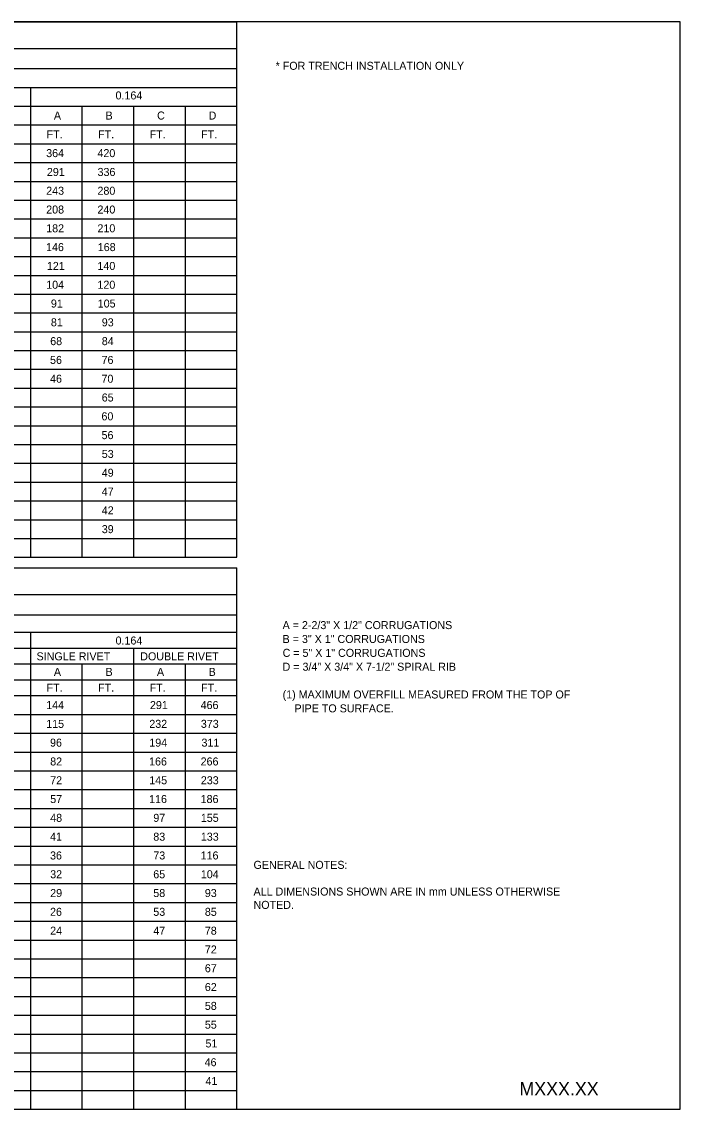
# Model space of a CAD drawing. Extents: x -439.1 to -407.9, y -458.1 to -436.2.
# Drawn here: x -420.2 to -407.86, y -458.05 to -437.68 of the extents above; entities that cross this region are included whole.
import ezdxf

# ---------------------------------------------------------------- set-up
doc = ezdxf.new("R2010")
doc.units = 0
for name, color, linetype in [('Draft_Named_Boundary', 7, 'Continuous'), ('Level 4', 7, 'Continuous'), ('Level 45', 7, 'Continuous'), ('Level 46', 7, 'Continuous')]:
    doc.layers.add(name, color=color, linetype=linetype)

msp = doc.modelspace()

# ---------------------------------------------------------------- linework, layer by layer
at = {"layer": 'Draft_Named_Boundary'}
msp.add_lwpolyline([(-439.109, -458.051), (-407.859, -458.051), (-407.859, -437.676), (-439.109, -437.676)], close=True, dxfattribs=at)
at = {"layer": 'Level 4'}
for p, q in [((-439.109, -437.676), (-416.17, -437.676)), ((-416.17, -447.71), (-416.17, -437.676)), ((-439.109, -438.177), (-416.17, -438.177)), ((-439.109, -438.552), (-416.17, -438.552)), ((-435.493, -438.905), (-416.17, -438.905)), ((-420.035, -447.71), (-420.035, -438.905)), ((-435.493, -439.257), (-416.17, -439.257)), ((-419.069, -447.71), (-419.069, -439.257)), ((-418.103, -447.71), (-418.103, -439.257)), ((-417.136, -447.71), (-417.136, -439.257)), ((-439.109, -439.609), (-416.17, -439.609)), ((-439.109, -439.961), (-416.17, -439.961)), ((-439.109, -440.313), (-416.17, -440.313)), ((-439.109, -440.666), (-416.17, -440.666)), ((-439.109, -441.018), (-416.17, -441.018)), ((-439.109, -441.37), (-416.17, -441.37)), ((-439.109, -441.722), (-416.17, -441.722)), ((-439.109, -442.075), (-416.17, -442.075)), ((-439.109, -442.427), (-416.17, -442.427)), ((-439.109, -442.779), (-416.17, -442.779)), ((-439.109, -443.131), (-416.17, -443.131)), ((-439.109, -443.483), (-416.17, -443.483)), ((-439.109, -443.836), (-416.17, -443.836)), ((-439.109, -444.188), (-416.17, -444.188)), ((-439.109, -444.54), (-416.17, -444.54)), ((-439.109, -444.892), (-416.17, -444.892)), ((-439.109, -445.245), (-416.17, -445.245)), ((-439.109, -445.597), (-416.17, -445.597)), ((-439.109, -445.949), (-416.17, -445.949)), ((-439.109, -446.301), (-416.17, -446.301)), ((-439.109, -446.654), (-416.17, -446.654)), ((-439.109, -447.006), (-416.17, -447.006)), ((-439.109, -447.358), (-416.17, -447.358)), ((-439.109, -447.71), (-416.17, -447.71)), ((-439.109, -447.908), (-416.17, -447.908)), ((-416.17, -458.051), (-416.17, -447.908)), ((-439.109, -448.409), (-416.17, -448.409)), ((-439.109, -448.785), (-416.17, -448.785)), ((-435.493, -449.113), (-416.17, -449.113)), ((-420.035, -458.051), (-420.035, -449.113)), ((-435.493, -449.411), (-416.17, -449.411)), ((-418.103, -458.051), (-418.103, -449.411)), ((-435.493, -449.708), (-416.17, -449.708)), ((-419.069, -458.051), (-419.069, -449.708)), ((-417.136, -458.051), (-417.136, -449.708)), ((-439.109, -450.005), (-416.17, -450.005)), ((-439.109, -450.302), (-416.17, -450.302)), ((-439.109, -450.654), (-416.17, -450.654)), ((-439.109, -451.006), (-416.17, -451.006)), ((-439.109, -451.359), (-416.17, -451.359)), ((-439.109, -451.711), (-416.17, -451.711)), ((-439.109, -452.063), (-416.17, -452.063)), ((-439.109, -452.415), (-416.17, -452.415)), ((-439.109, -452.767), (-416.17, -452.767)), ((-439.109, -453.12), (-416.17, -453.12)), ((-439.109, -453.472), (-416.17, -453.472)), ((-439.109, -453.824), (-416.17, -453.824)), ((-439.109, -454.176), (-416.17, -454.176)), ((-439.109, -454.529), (-416.17, -454.529)), ((-439.109, -454.881), (-416.17, -454.881)), ((-439.109, -455.233), (-416.17, -455.233)), ((-439.109, -455.585), (-416.17, -455.585)), ((-439.109, -455.937), (-416.17, -455.937)), ((-439.109, -456.29), (-416.17, -456.29)), ((-439.109, -456.642), (-416.17, -456.642)), ((-439.109, -456.994), (-416.17, -456.994)), ((-439.109, -457.346), (-416.17, -457.346)), ((-439.109, -457.699), (-416.17, -457.699)), ((-439.109, -458.051), (-416.17, -458.051))]:
    msp.add_line(p, q, dxfattribs=at)

# ---------------------------------------------------------------- texts
for s, p in [('* FOR TRENCH INSTALLATION ONLY', (-415.445, -438.576)), ('0.164', (-418.446, -439.131)), ('A', (-419.602, -439.508)), ('B', (-418.633, -439.508)), ('C', (-417.667, -439.508)), ('D', (-416.701, -439.508)), ('FT.', (-419.739, -439.86)), ('FT.', (-418.773, -439.86)), ('FT.', (-417.807, -439.86)), ('FT.', (-416.841, -439.86)), ('364', (-419.746, -440.212)), ('420', (-418.785, -440.212)), ('291', (-419.733, -440.565)), ('336', (-418.783, -440.565)), ('243', (-419.746, -440.917)), ('280', (-418.785, -440.917)), ('208', (-419.746, -441.269)), ('240', (-418.785, -441.269)), ('182', (-419.746, -441.621)), ('210', (-418.785, -441.621)), ('146', (-419.749, -441.973)), ('168', (-418.779, -441.973)), ('121', (-419.733, -442.326)), ('140', (-418.785, -442.326)), ('104', (-419.746, -442.678)), ('120', (-418.785, -442.678)), ('91', (-419.658, -443.03)), ('105', (-418.78, -443.03)), ('81', (-419.658, -443.382)), ('93', (-418.704, -443.382)), ('68', (-419.671, -443.735)), ('84', (-418.704, -443.735)), ('56', (-419.674, -444.087)), ('76', (-418.708, -444.087)), ('46', (-419.674, -444.439)), ('70', (-418.71, -444.439)), ('65', (-418.705, -444.791)), ('60', (-418.71, -445.143)), ('56', (-418.708, -445.496)), ('53', (-418.704, -445.848)), ('49', (-418.704, -446.2)), ('47', (-418.704, -446.552)), ('42', (-418.704, -446.905)), ('39', (-418.704, -447.257)), ('0.164', (-418.446, -449.344)), ('SINGLE RIVET', (-419.927, -449.64)), ('DOUBLE RIVET', (-417.983, -449.64)), ('A', (-419.602, -449.931)), ('B', (-418.633, -449.931)), ('A', (-417.67, -449.931)), ('B', (-416.701, -449.931)), ('FT.', (-419.739, -450.228)), ('FT.', (-418.773, -450.228)), ('FT.', (-417.807, -450.228)), ('FT.', (-416.841, -450.228)), ('144', (-419.746, -450.553)), ('291', (-417.801, -450.553)), ('466', (-416.851, -450.553)), ('115', (-419.746, -450.905)), ('232', (-417.813, -450.905)), ('373', (-416.847, -450.905)), ('96', (-419.674, -451.257)), ('194', (-417.813, -451.257)), ('311', (-416.835, -451.257)), ('82', (-419.671, -451.61)), ('166', (-417.817, -451.61)), ('266', (-416.851, -451.61)), ('72', (-419.671, -451.962)), ('145', (-417.814, -451.962)), ('233', (-416.847, -451.962)), ('57', (-419.671, -452.314)), ('116', (-417.817, -452.314)), ('186', (-416.851, -452.314)), ('48', (-419.671, -452.666)), ('97', (-417.738, -452.666)), ('155', (-416.847, -452.666)), ('41', (-419.673, -453.017)), ('83', (-417.738, -453.019)), ('133', (-416.847, -453.019)), ('36', (-419.674, -453.371)), ('73', (-417.738, -453.371)), ('116', (-416.851, -453.371)), ('32', (-419.671, -453.723)), ('65', (-417.739, -453.723)), ('104', (-416.847, -453.723)), ('29', (-419.671, -454.075)), ('58', (-417.738, -454.075)), ('93', (-416.772, -454.075)), ('26', (-419.674, -454.427)), ('53', (-417.738, -454.427)), ('85', (-416.772, -454.427)), ('24', (-419.671, -454.78)), ('47', (-417.738, -454.78)), ('78', (-416.772, -454.78)), ('72', (-416.772, -455.132)), ('67', (-416.772, -455.484)), ('62', (-416.772, -455.836)), ('58', (-416.772, -456.189)), ('55', (-416.772, -456.541)), ('51', (-416.76, -456.893)), ('46', (-416.776, -457.245)), ('41', (-416.76, -457.597))]:
    msp.add_text(s, height=0.15, dxfattribs=at).set_placement(p)
at = {"layer": 'Level 45'}
for s, p in [('A = 2-2/3" X 1/2" CORRUGATIONS', (-415.314, -449.055)), ('B = 3" X 1" CORRUGATIONS', (-415.314, -449.315)), ('C = 5" X 1" CORRUGATIONS ', (-415.314, -449.575)), ('D = 3/4" X 3/4" X 7-1/2" SPIRAL RIB', (-415.314, -449.835)), ('(1) MAXIMUM OVERFILL MEASURED FROM THE TOP OF ', (-415.314, -450.355)), ('    PIPE TO SURFACE.  ', (-415.314, -450.615))]:
    msp.add_text(s, height=0.15, dxfattribs=at).set_placement(p)
at = {"layer": 'Level 46'}
for s, height, p in [('GENERAL NOTES:', 0.15, (-415.859, -453.547)), ('ALL DIMENSIONS SHOWN ARE IN mm UNLESS OTHERWISE ', 0.15, (-415.859, -454.047)), ('NOTED.', 0.15, (-415.859, -454.297)), ('MXXX.XX', 0.25, (-410.875, -457.792))]:
    msp.add_text(s, height=height, dxfattribs=at).set_placement(p)

doc.saveas('drawing.dxf')
